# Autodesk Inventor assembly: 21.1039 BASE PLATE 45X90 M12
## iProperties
Created: 2007-03
Part Number: 21.1039 BASE PLATE 45X90 M12
Document SubType Name: Assembly
Designer: Andy Moles
Author: Andy Moles
